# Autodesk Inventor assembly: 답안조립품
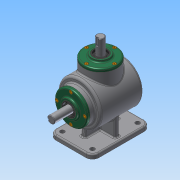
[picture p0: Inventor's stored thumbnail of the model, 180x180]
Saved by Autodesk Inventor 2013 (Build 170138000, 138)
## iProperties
Created: 2016-09
Part Number: 답안조립품
Document SubType Name: Assembly
Designer: Administrator
Author: Administrator
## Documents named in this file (14)
- C:\Users\Administrator\Desktop\460908V1007\답안조립품.iam
- C:\Users\Administrator\Desktop\460908V1007\본체.ipt
- C:\Users\Administrator\Desktop\460908V1007\커버.ipt
- C:\Users\Administrator\Desktop\460908V1007\베어링 6203.ipt
- C:\Users\Administrator\Desktop\460908V1007\메인 축.ipt
- 메인 축.ipt
- C:\Users\Administrator\Desktop\460908V1007\서브 축.ipt
- 서브 축.ipt
- C:\Users\Administrator\Desktop\460908V1007\오일실 17 32 8.ipt
- C:\Users\Administrator\Desktop\460908V1007\키 5x5.ipt
- C:\Users\Administrator\Desktop\460908V1007\키 4x4.ipt
- C:\Users\Administrator\Desktop\460908V1007\메인 베벨기어.ipt
- C:\Users\Administrator\Desktop\460908V1007\서브 베벨기어.ipt
- C:\Users\Administrator\Desktop\460908V1007\M4.ipt
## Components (8 placed, 1 different names)
1. M4:2
2. M4:3
3. M4:4
4. M4:5
5. M4:1
6. M4:6
7. M4:7
8. M4:8
